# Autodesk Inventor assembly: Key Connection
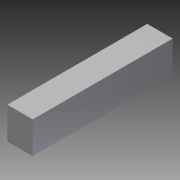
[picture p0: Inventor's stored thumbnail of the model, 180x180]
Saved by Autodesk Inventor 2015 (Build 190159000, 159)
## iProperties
Created: 2007-02
Part Number: Key Connection
Document SubType Name: Assembly
Designer: Autodesk, Inc.
Mass: 13.8362 g
Surface Area: 10.9879 cm^2
Volume: 1.76033 cm^3
Density: 7.86 g/cm^3
ClientObjectVersion: 1
Author: Autodesk, Inc.
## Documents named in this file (2)
- C:\Users\Public\Documents\Autodesk\Inventor 2015\Samples\Models\Assemblies\Blower\Blower\Design Accelerator\Key Connection4.iam
- C:\Users\Public\Documents\Autodesk\Inventor 2015\Samples\Standard Parts\en-US\Usas b17.1(1)\USAS B17.1 - 5_16 x 1_4 x 1 3_8.ipt
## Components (1 placed, 1 different names)
1. USAS B17.1 - 5/16 x 1/4 x 1 3/8:1
